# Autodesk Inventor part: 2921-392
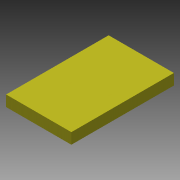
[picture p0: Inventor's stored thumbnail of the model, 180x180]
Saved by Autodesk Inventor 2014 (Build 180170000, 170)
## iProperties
Company: NHTSA/VRTC
Created: 2012-02
Part Number: 2921-392
Project: CHILD SIDE IMPACT SLED
Material: Polyurethane Foam
Description: SEAT BACK CUSHION
Document SubType Name: Modeling
Designer: Mike Vnvoorhis
Mass: 15957.2 g
Surface Area: 8742.4 cm^2
Volume: 25410 cm^3
Density: 0.627988 g/cm^3
Appearance: Canary
Title: Seat Back Cushion
Subject: Child Side Impact Sled
Author: Dave Walker
Comments: POLYURETHANE FOAM DENSITY ACCORDING TO ISO 485 (kg/m³)  BEARING STRENGTH ACCORDING TO ISO 2439B (N) p - 25% p - 40% BEARING STRENGTH FACTOR ACCORDEING TO ISO 3386 (kPa) ELONGATION AT RUPTURE ACCORDING
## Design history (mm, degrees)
sketch "Sketch1"
  geometry: L1 (330, 210)-(330, -210); L2 (330, -210)-(-330, -210); L3 (-330, -210)-(-330, 210); L4 (0, 294)-(0, -294) reference; L5 (-462, 0)-(462, 0) reference; L6 (-330, 210)-(330, 210); 1 further point
  constraints: 8 end point, 2 parallel, 1 horizontal, 1 midpoint, 1 perpendicular, 1 point on line, 2 other
  dimensions: "d0" = 660 distance of L3.end L1.start; "d1" = 420 distance of L2.end L3.end
extrude "Extrusion1" new body sketch "Sketch1" distance "d7" = 70; taper "d8" = 0 deg
body "Solid1"
